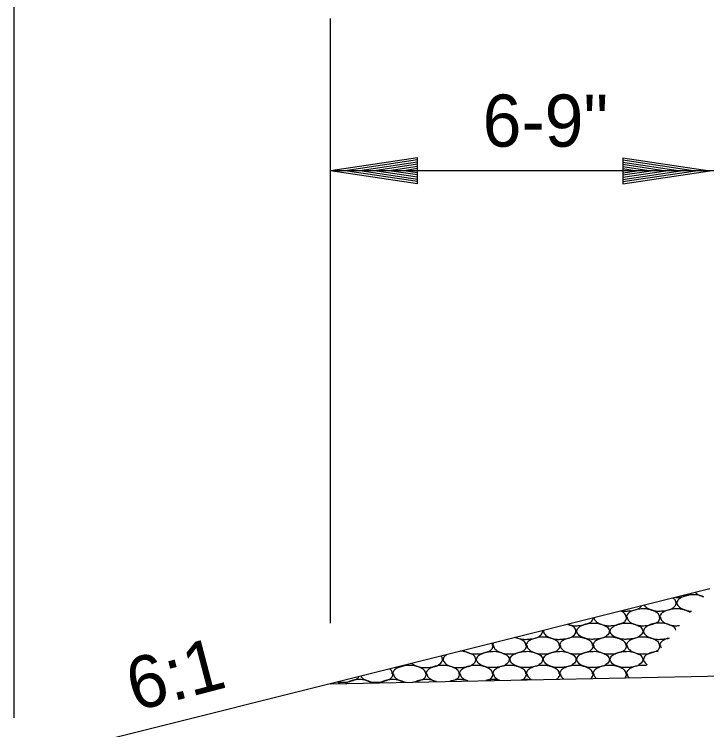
# Model space of a CAD drawing. Extents: x 138 to 3619, y -519 to 1449.
# Drawn here: x 381.3 to 460.9, y 521.1 to 603.4 of the extents above; entities that cross this region are included whole.
import ezdxf

# ---------------------------------------------------------------- set-up
doc = ezdxf.new("R2010")
doc.units = 0
doc.layers.add('R_Annotation', color=7, linetype='Continuous')
doc.layers.add('R_Dimension', color=7, linetype='Continuous')

msp = doc.modelspace()

# ---------------------------------------------------------------- linework, layer by layer
at = {"layer": 'R_Annotation'}
for p, q in [((461.265, 537.259), (381.265, 517.259)), ((417.632, 526.35), (611.265, 530.223))]:
    msp.add_line(p, q, dxfattribs=at)
at = {"layer": 'R_Dimension'}
for p, q in [((381.265, 522.412), (381.265, 610.392)), ((417.632, 533.316), (417.632, 602.892)), ((427.632, 586.892), (417.632, 585.392)), ((427.632, 586.642), (419.302, 585.392)), ((427.632, 586.387), (421.022, 585.392)), ((427.632, 583.892), (427.632, 586.892)), ((451.265, 586.892), (461.265, 585.392)), ((451.265, 586.892), (451.265, 583.892)), ((451.265, 586.642), (459.595, 585.392)), ((451.265, 586.387), (457.875, 585.392)), ((427.632, 586.137), (422.687, 585.392)), ((427.632, 585.882), (424.382, 585.392)), ((427.632, 585.627), (426.052, 585.392)), ((451.265, 586.137), (456.21, 585.392)), ((451.265, 585.877), (454.515, 585.392)), ((451.265, 585.627), (452.845, 585.392)), ((804.897, 585.392), (417.632, 585.392)), ((427.632, 583.892), (417.632, 585.392)), ((427.632, 584.142), (419.302, 585.392)), ((427.632, 584.397), (421.022, 585.392)), ((427.632, 584.647), (422.687, 585.392)), ((427.632, 584.907), (424.382, 585.392)), ((427.632, 585.157), (426.052, 585.392)), ((451.265, 583.892), (461.265, 585.392)), ((451.265, 584.902), (454.515, 585.392)), ((451.265, 584.397), (457.875, 585.392)), ((451.265, 584.142), (459.595, 585.392)), ((451.265, 584.647), (456.21, 585.392)), ((451.265, 585.157), (452.845, 585.392))]:
    msp.add_line(p, q, dxfattribs=at)
for points in [[(459.613, 536.845), (459.623, 536.833), (459.702, 536.741), (459.937, 536.583), (460.233, 536.449), (460.461, 536.379), (460.524, 536.362)], [(453.733, 535.376), (453.763, 535.327), (453.87, 535.186), (454.132, 535.008), (454.578, 534.818), (455.064, 534.703), (455.561, 534.709), (456.019, 534.747), (456.361, 534.802), (456.687, 534.878), (456.987, 535.052), (457.215, 535.223), (457.374, 535.466), (457.39, 535.676), (457.347, 535.883), (457.19, 536.091), (457.115, 536.15), (457.03, 536.2)], [(457.356, 536.281), (457.379, 536.282), (457.402, 536.283), (457.425, 536.284)], [(457.425, 536.284), (457.445, 536.284), (457.631, 536.282), (457.998, 536.31), (458.475, 536.45), (458.782, 536.552), (458.988, 536.641), (459.047, 536.675), (459.101, 536.718)], [(459.345, 536.584), (459.125, 536.587), (458.619, 536.521), (458.169, 536.372), (457.754, 536.15), (457.64, 536.029), (457.482, 535.792), (457.458, 535.569), (457.569, 535.358), (457.75, 535.155), (457.972, 535.008), (458.418, 534.818), (458.842, 534.714), (459.108, 534.704), (459.155, 534.703)], [(460.526, 536.364), (460.518, 536.367), (460.36, 536.421), (460.108, 536.5), (459.724, 536.587), (459.484, 536.596), (459.345, 536.584)], [(451.149, 534.729), (451.21, 534.72), (451.382, 534.702), (451.721, 534.709), (452.179, 534.747), (452.521, 534.802), (452.847, 534.878), (453.113, 535.033), (453.326, 535.187), (453.416, 535.296)], [(451.62, 534.004), (451.62, 534.009), (451.618, 534.14), (451.581, 534.266), (451.417, 534.492), (451.258, 534.589), (451.089, 534.675), (451.033, 534.701)], [(453.54, 534.964), (453.32, 534.967), (452.814, 534.901), (452.364, 534.752), (451.949, 534.53), (451.816, 534.414), (451.685, 534.17), (451.671, 534.096), (451.664, 534.014), (451.664, 534.008), (451.665, 534.004)], [(453.585, 534.964), (453.57, 534.963), (453.555, 534.964), (453.54, 534.964)], [(455.46, 534.004), (455.46, 534.009), (455.458, 534.14), (455.421, 534.266), (455.257, 534.492), (455.054, 534.614), (454.695, 534.772), (454.348, 534.88), (453.964, 534.967), (453.724, 534.976), (453.585, 534.964)], [(457.38, 534.964), (457.16, 534.967), (456.654, 534.901), (456.204, 534.752), (455.789, 534.53), (455.656, 534.414), (455.525, 534.17), (455.511, 534.096), (455.504, 534.014), (455.504, 534.008), (455.505, 534.004)], [(457.425, 534.964), (457.41, 534.963), (457.395, 534.964), (457.38, 534.964)], [(459.017, 534.537), (458.974, 534.567), (458.829, 534.646), (458.535, 534.772), (458.188, 534.88), (457.804, 534.967), (457.564, 534.976), (457.425, 534.964)], [(445.905, 533.029), (445.925, 533.029), (446.111, 533.027), (446.478, 533.055), (446.955, 533.195), (447.262, 533.297), (447.564, 533.427), (447.696, 533.542), (447.814, 533.769), (447.831, 533.834), (447.837, 533.902)], [(447.918, 533.922), (447.936, 533.785), (448.089, 533.557), (448.417, 533.328), (448.863, 533.142), (449.24, 533.037), (449.555, 533.025), (449.65, 533.024), (449.745, 533.029)], [(449.745, 533.029), (449.765, 533.029), (449.951, 533.027), (450.318, 533.055), (450.795, 533.195), (451.102, 533.297), (451.404, 533.427), (451.536, 533.542), (451.663, 533.787), (451.68, 533.886), (451.68, 533.989), (451.68, 534.004)], [(451.755, 534.004), (451.754, 533.989), (451.751, 533.819), (451.857, 533.675), (452.033, 533.477), (452.257, 533.328), (452.703, 533.142), (453.08, 533.037), (453.395, 533.025), (453.49, 533.024), (453.585, 533.029)], [(453.585, 533.029), (453.605, 533.029), (453.791, 533.027), (454.158, 533.055), (454.635, 533.195), (454.942, 533.297), (455.244, 533.427), (455.376, 533.542), (455.503, 533.787), (455.52, 533.886), (455.52, 533.989), (455.52, 534.004)], [(455.595, 534.004), (455.594, 533.989), (455.591, 533.819), (455.697, 533.675), (455.873, 533.477), (456.097, 533.328), (456.543, 533.142), (456.92, 533.037), (457.235, 533.025), (457.33, 533.024), (457.425, 533.029)], [(442.111, 532.47), (442.106, 532.441), (442.121, 532.27), (442.209, 532.103), (442.39, 531.9), (442.612, 531.753), (443.058, 531.563), (443.544, 531.448), (444.041, 531.454), (444.499, 531.492), (444.841, 531.547), (445.167, 531.623), (445.467, 531.797), (445.695, 531.968), (445.854, 532.211), (445.87, 532.421), (445.827, 532.628), (445.651, 532.861), (445.454, 532.979), (445.181, 533.106), (445.013, 533.16), (444.95, 533.18)], [(444.936, 533.176), (444.949, 533.172), (445.175, 533.1), (445.495, 533.026), (445.81, 533.024), (445.905, 533.029)], [(447.825, 533.329), (447.605, 533.332), (447.099, 533.266), (446.649, 533.117), (446.234, 532.895), (446.12, 532.774), (445.962, 532.537), (445.938, 532.314), (446.049, 532.103), (446.23, 531.9), (446.452, 531.753), (446.898, 531.563), (447.384, 531.448), (447.881, 531.454), (448.339, 531.492), (448.681, 531.547), (449.007, 531.623), (449.307, 531.797), (449.535, 531.968), (449.694, 532.211), (449.71, 532.421), (449.667, 532.628), (449.491, 532.861), (449.294, 532.979), (448.935, 533.137), (448.588, 533.245), (448.204, 533.332), (447.964, 533.341), (447.825, 533.329)], [(451.665, 533.329), (451.445, 533.332), (450.939, 533.266), (450.489, 533.117), (450.074, 532.895), (449.96, 532.774), (449.802, 532.537), (449.778, 532.314), (449.889, 532.103), (450.07, 531.9), (450.292, 531.753), (450.738, 531.563), (451.224, 531.448), (451.721, 531.454), (452.179, 531.492), (452.521, 531.547), (452.847, 531.623), (453.147, 531.797), (453.375, 531.968), (453.534, 532.211), (453.55, 532.421), (453.507, 532.628), (453.331, 532.861), (453.134, 532.979), (452.775, 533.137), (452.428, 533.245), (452.044, 533.332), (451.804, 533.341), (451.665, 533.329)], [(455.505, 533.329), (455.285, 533.332), (454.779, 533.266), (454.329, 533.117), (453.914, 532.895), (453.8, 532.774), (453.642, 532.537), (453.618, 532.314), (453.729, 532.103), (453.91, 531.9), (454.132, 531.753), (454.578, 531.563), (455.064, 531.448), (455.561, 531.454), (456.019, 531.492), (456.361, 531.547), (456.559, 531.593), (456.577, 531.598), (456.596, 531.604)], [(457.36, 532.529), (457.342, 532.602), (457.228, 532.824), (456.974, 532.979), (456.615, 533.137), (456.268, 533.245), (455.884, 533.332), (455.644, 533.341), (455.505, 533.329)], [(457.425, 533.029), (457.445, 533.029), (457.565, 533.027), (457.686, 533.034), (457.786, 533.045)], [(438.94, 531.677), (439.014, 531.644), (439.303, 531.541), (439.704, 531.448), (440.201, 531.454), (440.659, 531.492), (441.001, 531.547), (441.327, 531.623), (441.627, 531.797), (441.855, 531.968), (442.014, 532.211), (442.026, 532.32), (442.017, 532.425), (442.014, 532.446)], [(440.1, 530.749), (440.1, 530.754), (440.098, 530.885), (440.061, 531.011), (439.897, 531.237), (439.694, 531.359), (439.335, 531.517), (439.054, 531.603), (438.874, 531.648), (438.847, 531.654)], [(442.02, 531.709), (441.8, 531.712), (441.294, 531.646), (440.844, 531.497), (440.429, 531.275), (440.296, 531.159), (440.165, 530.915), (440.151, 530.841), (440.144, 530.759), (440.144, 530.753), (440.145, 530.749)], [(442.065, 531.709), (442.05, 531.708), (442.035, 531.709), (442.02, 531.709)], [(443.94, 530.749), (443.94, 530.754), (443.938, 530.885), (443.901, 531.011), (443.737, 531.237), (443.534, 531.359), (443.175, 531.517), (442.828, 531.625), (442.444, 531.712), (442.204, 531.721), (442.065, 531.709)], [(445.86, 531.709), (445.64, 531.712), (445.134, 531.646), (444.684, 531.497), (444.269, 531.275), (444.136, 531.159), (444.005, 530.915), (443.991, 530.841), (443.984, 530.759), (443.984, 530.753), (443.985, 530.749)], [(445.905, 531.709), (445.89, 531.708), (445.875, 531.709), (445.86, 531.709)], [(447.78, 530.749), (447.78, 530.754), (447.778, 530.885), (447.741, 531.011), (447.577, 531.237), (447.374, 531.359), (447.015, 531.517), (446.668, 531.625), (446.284, 531.712), (446.044, 531.721), (445.905, 531.709)], [(449.7, 531.709), (449.48, 531.712), (448.974, 531.646), (448.524, 531.497), (448.109, 531.275), (447.976, 531.159), (447.845, 530.915), (447.831, 530.841), (447.824, 530.759), (447.824, 530.753), (447.825, 530.749)], [(449.745, 531.709), (449.73, 531.708), (449.715, 531.709), (449.7, 531.709)], [(451.62, 530.749), (451.62, 530.754), (451.618, 530.885), (451.581, 531.011), (451.417, 531.237), (451.214, 531.359), (450.855, 531.517), (450.508, 531.625), (450.124, 531.712), (449.884, 531.721), (449.745, 531.709)], [(453.54, 531.709), (453.32, 531.712), (452.814, 531.646), (452.364, 531.497), (451.949, 531.275), (451.816, 531.159), (451.685, 530.915), (451.671, 530.841), (451.664, 530.759), (451.664, 530.753), (451.665, 530.749)], [(453.585, 531.709), (453.57, 531.708), (453.555, 531.709), (453.54, 531.709)], [(455.46, 530.749), (455.46, 530.754), (455.458, 530.885), (455.421, 531.011), (455.257, 531.237), (455.054, 531.359), (454.695, 531.517), (454.348, 531.625), (453.964, 531.712), (453.724, 531.721), (453.585, 531.709)], [(456.598, 531.606), (456.375, 531.552), (456.166, 531.477), (455.789, 531.275), (455.656, 531.159), (455.525, 530.915), (455.511, 530.841), (455.504, 530.759), (455.504, 530.753), (455.505, 530.749)], [(434.385, 529.774), (434.405, 529.774), (434.591, 529.772), (434.958, 529.8), (435.435, 529.94), (435.742, 530.042), (436.044, 530.172), (436.176, 530.287), (436.303, 530.532), (436.32, 530.631), (436.32, 530.734), (436.32, 530.749)], [(436.26, 530.749), (436.26, 530.754), (436.259, 530.838), (436.243, 530.921), (436.212, 530.995)], [(436.395, 531.041), (436.385, 531.024), (436.329, 530.934), (436.311, 530.841), (436.304, 530.759), (436.304, 530.753), (436.305, 530.749)], [(436.395, 530.749), (436.394, 530.734), (436.391, 530.564), (436.497, 530.42), (436.673, 530.222), (436.897, 530.073), (437.343, 529.887), (437.72, 529.782), (438.035, 529.77), (438.13, 529.769), (438.225, 529.774)], [(438.225, 529.774), (438.245, 529.774), (438.431, 529.772), (438.798, 529.8), (439.275, 529.94), (439.582, 530.042), (439.884, 530.172), (440.016, 530.287), (440.143, 530.532), (440.16, 530.631), (440.16, 530.734), (440.16, 530.749)], [(440.235, 530.749), (440.234, 530.734), (440.231, 530.564), (440.337, 530.42), (440.513, 530.222), (440.737, 530.073), (441.183, 529.887), (441.56, 529.782), (441.875, 529.77), (441.97, 529.769), (442.065, 529.774)], [(442.065, 529.774), (442.085, 529.774), (442.271, 529.772), (442.638, 529.8), (443.115, 529.94), (443.422, 530.042), (443.724, 530.172), (443.856, 530.287), (443.983, 530.532), (444, 530.631), (444, 530.734), (444, 530.749)], [(444.075, 530.749), (444.074, 530.734), (444.071, 530.564), (444.177, 530.42), (444.353, 530.222), (444.577, 530.073), (445.023, 529.887), (445.4, 529.782), (445.715, 529.77), (445.81, 529.769), (445.905, 529.774)], [(445.905, 529.774), (445.925, 529.774), (446.111, 529.772), (446.478, 529.8), (446.955, 529.94), (447.262, 530.042), (447.564, 530.172), (447.696, 530.287), (447.823, 530.532), (447.84, 530.631), (447.84, 530.734), (447.84, 530.749)], [(447.915, 530.749), (447.914, 530.734), (447.911, 530.564), (448.017, 530.42), (448.193, 530.222), (448.417, 530.073), (448.863, 529.887), (449.24, 529.782), (449.555, 529.77), (449.65, 529.769), (449.745, 529.774)], [(449.745, 529.774), (449.765, 529.774), (449.951, 529.772), (450.318, 529.8), (450.795, 529.94), (451.102, 530.042), (451.404, 530.172), (451.536, 530.287), (451.663, 530.532), (451.68, 530.631), (451.68, 530.734), (451.68, 530.749)], [(451.755, 530.749), (451.754, 530.734), (451.751, 530.564), (451.857, 530.42), (452.033, 530.222), (452.257, 530.073), (452.703, 529.887), (453.08, 529.782), (453.395, 529.77), (453.49, 529.769), (453.585, 529.774)], [(453.585, 529.774), (453.605, 529.774), (453.791, 529.772), (454.158, 529.8), (454.635, 529.94), (454.942, 530.042), (455.244, 530.172), (455.376, 530.287), (455.503, 530.532), (455.52, 530.631), (455.52, 530.734), (455.52, 530.749)], [(455.595, 530.749), (455.594, 530.734), (455.592, 530.638), (455.626, 530.55), (455.667, 530.479)], [(426.991, 528.69), (427.051, 528.629), (427.264, 528.492), (427.698, 528.308), (428.184, 528.193), (428.681, 528.199), (429.139, 528.237), (429.481, 528.292), (429.807, 528.368), (430.107, 528.542), (430.335, 528.713), (430.494, 528.956), (430.51, 529.166), (430.467, 529.373), (430.369, 529.503), (430.358, 529.516), (430.347, 529.529)], [(430.964, 529.683), (430.837, 529.6), (430.742, 529.492), (430.602, 529.282), (430.578, 529.059), (430.689, 528.848), (430.87, 528.645), (431.092, 528.498), (431.538, 528.308), (432.024, 528.193), (432.521, 528.199), (432.979, 528.237), (433.321, 528.292), (433.647, 528.368), (433.947, 528.542), (434.175, 528.713), (434.334, 528.956), (434.35, 529.166), (434.307, 529.373), (434.131, 529.606), (433.934, 529.724), (433.575, 529.882), (433.228, 529.99), (432.87, 530.07), (432.658, 530.083), (432.545, 530.079)], [(432.909, 530.17), (432.935, 530.151), (433.113, 530.046), (433.503, 529.887), (433.88, 529.782), (434.195, 529.77), (434.29, 529.769), (434.385, 529.774)], [(436.305, 530.074), (436.085, 530.077), (435.579, 530.011), (435.129, 529.862), (434.714, 529.64), (434.6, 529.519), (434.442, 529.282), (434.418, 529.059), (434.529, 528.848), (434.71, 528.645), (434.932, 528.498), (435.378, 528.308), (435.864, 528.193), (436.361, 528.199), (436.819, 528.237), (437.161, 528.292), (437.487, 528.368), (437.787, 528.542), (438.015, 528.713), (438.174, 528.956), (438.19, 529.166), (438.147, 529.373), (437.971, 529.606), (437.774, 529.724), (437.415, 529.882), (437.068, 529.99), (436.684, 530.077), (436.444, 530.086), (436.305, 530.074)], [(440.145, 530.074), (439.925, 530.077), (439.419, 530.011), (438.969, 529.862), (438.554, 529.64), (438.44, 529.519), (438.282, 529.282), (438.258, 529.059), (438.369, 528.848), (438.55, 528.645), (438.772, 528.498), (439.218, 528.308), (439.704, 528.193), (440.201, 528.199), (440.659, 528.237), (441.001, 528.292), (441.327, 528.368), (441.627, 528.542), (441.855, 528.713), (442.014, 528.956), (442.03, 529.166), (441.987, 529.373), (441.811, 529.606), (441.614, 529.724), (441.255, 529.882), (440.908, 529.99), (440.524, 530.077), (440.284, 530.086), (440.145, 530.074)], [(443.985, 530.074), (443.765, 530.077), (443.259, 530.011), (442.809, 529.862), (442.394, 529.64), (442.28, 529.519), (442.122, 529.282), (442.098, 529.059), (442.209, 528.848), (442.39, 528.645), (442.612, 528.498), (443.058, 528.308), (443.544, 528.193), (444.041, 528.199), (444.499, 528.237), (444.841, 528.292), (445.167, 528.368), (445.467, 528.542), (445.695, 528.713), (445.854, 528.956), (445.87, 529.166), (445.827, 529.373), (445.651, 529.606), (445.454, 529.724), (445.095, 529.882), (444.748, 529.99), (444.364, 530.077), (444.124, 530.086), (443.985, 530.074)], [(447.825, 530.074), (447.605, 530.077), (447.099, 530.011), (446.649, 529.862), (446.234, 529.64), (446.12, 529.519), (445.962, 529.282), (445.938, 529.059), (446.049, 528.848), (446.23, 528.645), (446.452, 528.498), (446.898, 528.308), (447.384, 528.193), (447.881, 528.199), (448.339, 528.237), (448.681, 528.292), (449.007, 528.368), (449.307, 528.542), (449.535, 528.713), (449.694, 528.956), (449.71, 529.166), (449.667, 529.373), (449.491, 529.606), (449.294, 529.724), (448.935, 529.882), (448.588, 529.99), (448.204, 530.077), (447.964, 530.086), (447.825, 530.074)], [(451.665, 530.074), (451.445, 530.077), (450.939, 530.011), (450.489, 529.862), (450.074, 529.64), (449.96, 529.519), (449.802, 529.282), (449.778, 529.059), (449.889, 528.848), (450.07, 528.645), (450.292, 528.498), (450.738, 528.308), (451.224, 528.193), (451.721, 528.199), (452.179, 528.237), (452.521, 528.292), (452.847, 528.368), (453.147, 528.542), (453.375, 528.713), (453.534, 528.956), (453.55, 529.166), (453.507, 529.373), (453.331, 529.606), (453.134, 529.724), (452.775, 529.882), (452.428, 529.99), (452.044, 530.077), (451.804, 530.086), (451.665, 530.074)], [(455.328, 530.069), (455.167, 530.058), (454.725, 529.993), (454.329, 529.862), (453.914, 529.64), (453.8, 529.519), (453.642, 529.282), (453.618, 529.059), (453.729, 528.848), (453.91, 528.645), (453.98, 528.592), (454.067, 528.543), (454.067, 528.542)], [(424.74, 527.494), (424.74, 527.499), (424.738, 527.63), (424.701, 527.756), (424.563, 527.946), (424.498, 528.002), (424.425, 528.049)], [(426.66, 528.454), (426.44, 528.457), (425.934, 528.391), (425.484, 528.242), (425.069, 528.02), (424.936, 527.904), (424.805, 527.66), (424.791, 527.586), (424.784, 527.504), (424.784, 527.498), (424.785, 527.494)], [(425.15, 528.23), (425.193, 528.234), (425.419, 528.257), (425.641, 528.292), (425.936, 528.361), (426.04, 528.416), (426.144, 528.478)], [(426.705, 528.454), (426.69, 528.453), (426.675, 528.454), (426.66, 528.454)], [(428.58, 527.494), (428.58, 527.499), (428.578, 527.63), (428.541, 527.756), (428.377, 527.982), (428.174, 528.104), (427.815, 528.262), (427.468, 528.37), (427.084, 528.457), (426.844, 528.466), (426.705, 528.454)], [(430.5, 528.454), (430.28, 528.457), (429.774, 528.391), (429.324, 528.242), (428.909, 528.02), (428.776, 527.904), (428.645, 527.66), (428.631, 527.586), (428.624, 527.504), (428.624, 527.498), (428.625, 527.494)], [(430.545, 528.454), (430.53, 528.453), (430.515, 528.454), (430.5, 528.454)], [(432.42, 527.494), (432.42, 527.499), (432.418, 527.63), (432.381, 527.756), (432.217, 527.982), (432.014, 528.104), (431.655, 528.262), (431.308, 528.37), (430.924, 528.457), (430.684, 528.466), (430.545, 528.454)], [(434.34, 528.454), (434.12, 528.457), (433.614, 528.391), (433.164, 528.242), (432.749, 528.02), (432.616, 527.904), (432.485, 527.66), (432.471, 527.586), (432.464, 527.504), (432.464, 527.498), (432.465, 527.494)], [(434.385, 528.454), (434.37, 528.453), (434.355, 528.454), (434.34, 528.454)], [(436.26, 527.494), (436.26, 527.499), (436.258, 527.63), (436.221, 527.756), (436.057, 527.982), (435.854, 528.104), (435.495, 528.262), (435.148, 528.37), (434.764, 528.457), (434.524, 528.466), (434.385, 528.454)], [(438.18, 528.454), (437.96, 528.457), (437.454, 528.391), (437.004, 528.242), (436.589, 528.02), (436.456, 527.904), (436.325, 527.66), (436.311, 527.586), (436.304, 527.504), (436.304, 527.498), (436.305, 527.494)], [(438.225, 528.454), (438.21, 528.453), (438.195, 528.454), (438.18, 528.454)], [(440.1, 527.494), (440.1, 527.499), (440.098, 527.63), (440.061, 527.756), (439.897, 527.982), (439.694, 528.104), (439.335, 528.262), (438.988, 528.37), (438.604, 528.457), (438.364, 528.466), (438.225, 528.454)], [(442.02, 528.454), (441.8, 528.457), (441.294, 528.391), (440.844, 528.242), (440.429, 528.02), (440.296, 527.904), (440.165, 527.66), (440.151, 527.586), (440.144, 527.504), (440.144, 527.498), (440.145, 527.494)], [(442.065, 528.454), (442.05, 528.453), (442.035, 528.454), (442.02, 528.454)], [(443.94, 527.494), (443.94, 527.499), (443.938, 527.63), (443.901, 527.756), (443.737, 527.982), (443.534, 528.104), (443.175, 528.262), (442.828, 528.37), (442.444, 528.457), (442.204, 528.466), (442.065, 528.454)], [(445.86, 528.454), (445.64, 528.457), (445.134, 528.391), (444.684, 528.242), (444.269, 528.02), (444.136, 527.904), (444.005, 527.66), (443.991, 527.586), (443.984, 527.504), (443.984, 527.498), (443.985, 527.494)], [(445.905, 528.454), (445.89, 528.453), (445.875, 528.454), (445.86, 528.454)], [(447.78, 527.494), (447.78, 527.499), (447.778, 527.63), (447.741, 527.756), (447.577, 527.982), (447.374, 528.104), (447.015, 528.262), (446.668, 528.37), (446.284, 528.457), (446.044, 528.466), (445.905, 528.454)], [(449.7, 528.454), (449.48, 528.457), (448.974, 528.391), (448.524, 528.242), (448.109, 528.02), (447.976, 527.904), (447.845, 527.66), (447.831, 527.586), (447.824, 527.504), (447.824, 527.498), (447.825, 527.494)], [(449.745, 528.454), (449.73, 528.453), (449.715, 528.454), (449.7, 528.454)], [(451.62, 527.494), (451.62, 527.499), (451.618, 527.63), (451.581, 527.756), (451.417, 527.982), (451.214, 528.104), (450.855, 528.262), (450.508, 528.37), (450.124, 528.457), (449.884, 528.466), (449.745, 528.454)], [(453.54, 528.454), (453.32, 528.457), (452.814, 528.391), (452.364, 528.242), (451.949, 528.02), (451.816, 527.904), (451.685, 527.66), (451.671, 527.586), (451.664, 527.504), (451.664, 527.498), (451.665, 527.494)], [(453.585, 528.454), (453.57, 528.453), (453.555, 528.454), (453.54, 528.454)], [(453.984, 528.442), (453.852, 528.461), (453.717, 528.465), (453.585, 528.454)], [(419.025, 526.519), (419.045, 526.519), (419.231, 526.517), (419.598, 526.545), (420.075, 526.685), (420.382, 526.787), (420.673, 526.912), (420.799, 527.017), (420.883, 527.163)], [(421.11, 527.22), (421.147, 527.158), (421.261, 527.007), (421.537, 526.818), (421.983, 526.632), (422.36, 526.527), (422.675, 526.515), (422.77, 526.514), (422.865, 526.519)], [(422.865, 526.519), (422.885, 526.519), (423.071, 526.517), (423.438, 526.545), (423.915, 526.685), (424.222, 526.787), (424.524, 526.917), (424.656, 527.032), (424.783, 527.277), (424.8, 527.376), (424.8, 527.479), (424.8, 527.494)], [(424.875, 527.494), (424.874, 527.479), (424.871, 527.309), (424.977, 527.165), (425.153, 526.967), (425.377, 526.818), (425.795, 526.642), (426.145, 526.543), (426.334, 526.524)], [(427.104, 526.54), (427.156, 526.546), (427.385, 526.579), (427.755, 526.685), (428.062, 526.787), (428.364, 526.917), (428.496, 527.032), (428.623, 527.277), (428.64, 527.376), (428.64, 527.479), (428.64, 527.494)], [(428.715, 527.494), (428.714, 527.479), (428.711, 527.309), (428.817, 527.165), (428.993, 526.967), (429.217, 526.818), (429.517, 526.683), (429.748, 526.612), (429.815, 526.594)], [(431.362, 526.625), (431.445, 526.648), (431.679, 526.713), (431.902, 526.787), (432.204, 526.917), (432.336, 527.032), (432.463, 527.277), (432.48, 527.376), (432.48, 527.479), (432.48, 527.494)], [(432.555, 527.494), (432.554, 527.479), (432.551, 527.309), (432.657, 527.165), (432.833, 526.967), (433.045, 526.826), (433.267, 526.717), (433.417, 526.666)], [(435.487, 526.707), (435.622, 526.747), (435.934, 526.821), (436.176, 527.032), (436.303, 527.277), (436.32, 527.376), (436.32, 527.479), (436.32, 527.494)], [(436.395, 527.494), (436.394, 527.479), (436.391, 527.309), (436.497, 527.165), (436.673, 526.967), (436.825, 526.862), (436.99, 526.776), (437.072, 526.739)], [(439.576, 526.789), (439.626, 526.808), (439.842, 526.881), (440.016, 527.032), (440.143, 527.277), (440.16, 527.376), (440.16, 527.479), (440.16, 527.494)], [(440.235, 527.494), (440.234, 527.479), (440.231, 527.309), (440.337, 527.165), (440.513, 526.967), (440.615, 526.893), (440.731, 526.829), (440.762, 526.813)], [(443.611, 526.87), (443.749, 526.94), (443.864, 527.048), (443.983, 527.277), (444, 527.376), (444, 527.479), (444, 527.494)], [(444.075, 527.494), (444.074, 527.479), (444.071, 527.309), (444.177, 527.165), (444.342, 526.979), (444.402, 526.93), (444.47, 526.887)], [(447.577, 526.949), (447.659, 527.013), (447.803, 527.176), (447.84, 527.376), (447.84, 527.479), (447.84, 527.494)], [(447.915, 527.494), (447.914, 527.479), (447.911, 527.309), (448.017, 527.165), (448.152, 527.013), (448.179, 526.986), (448.208, 526.962)], [(451.503, 527.028), (451.548, 527.076), (451.65, 527.214), (451.68, 527.376), (451.68, 527.479), (451.68, 527.494)], [(451.755, 527.494), (451.754, 527.479), (451.751, 527.309), (451.857, 527.165), (451.967, 527.041), (451.969, 527.039), (451.971, 527.037)], [(418.723, 526.372), (418.673, 526.411), (418.57, 526.469), (418.463, 526.523), (418.414, 526.546)], [(418.453, 526.556), (418.548, 526.536), (418.738, 526.515), (418.93, 526.514), (419.025, 526.519)], [(420.945, 526.819), (420.725, 526.822), (420.219, 526.756), (419.769, 526.607), (419.47, 526.447), (419.426, 526.418), (419.384, 526.385)], [(422.449, 526.447), (422.433, 526.456), (422.318, 526.517), (422.055, 526.627), (421.708, 526.735), (421.324, 526.822), (421.084, 526.831), (420.945, 526.819)], [(424.785, 526.819), (424.565, 526.822), (424.059, 526.756), (423.609, 526.607), (423.354, 526.471), (423.349, 526.468), (423.343, 526.465)], [(426.147, 526.521), (426.08, 526.554), (425.862, 526.637), (425.548, 526.735), (425.164, 526.822), (424.924, 526.831), (424.785, 526.819)], [(428.625, 526.819), (428.405, 526.822), (427.953, 526.762), (427.544, 526.637), (427.343, 526.545)], [(429.82, 526.594), (429.807, 526.599), (429.644, 526.655), (429.388, 526.735), (429.004, 526.822), (428.764, 526.831), (428.625, 526.819)], [(432.465, 526.819), (432.245, 526.822), (431.868, 526.77), (431.517, 526.675), (431.379, 526.625)], [(433.44, 526.667), (433.351, 526.694), (433.167, 526.748), (432.844, 526.822), (432.604, 526.831), (432.465, 526.819)], [(436.305, 526.819), (436.085, 526.822), (435.808, 526.782), (435.539, 526.721), (435.487, 526.707)], [(437.03, 526.738), (437.023, 526.74), (436.922, 526.767), (436.684, 526.822), (436.444, 526.831), (436.305, 526.819)], [(440.145, 526.819), (440.02, 526.82), (439.895, 526.81), (439.77, 526.793)], [(440.532, 526.808), (440.403, 526.826), (440.273, 526.83), (440.145, 526.819)]]:
    msp.add_open_spline(points, degree=3, dxfattribs=at)

# ---------------------------------------------------------------- texts
at = {"layer": 'R_Annotation'}
msp.add_text('6-9"', height=6, dxfattribs=at).set_placement((435.127, 588.158))
msp.add_text('6:1', height=6, rotation=14.69451, dxfattribs=at).set_placement((395.115, 523.158))

doc.saveas('drawing.dxf')
